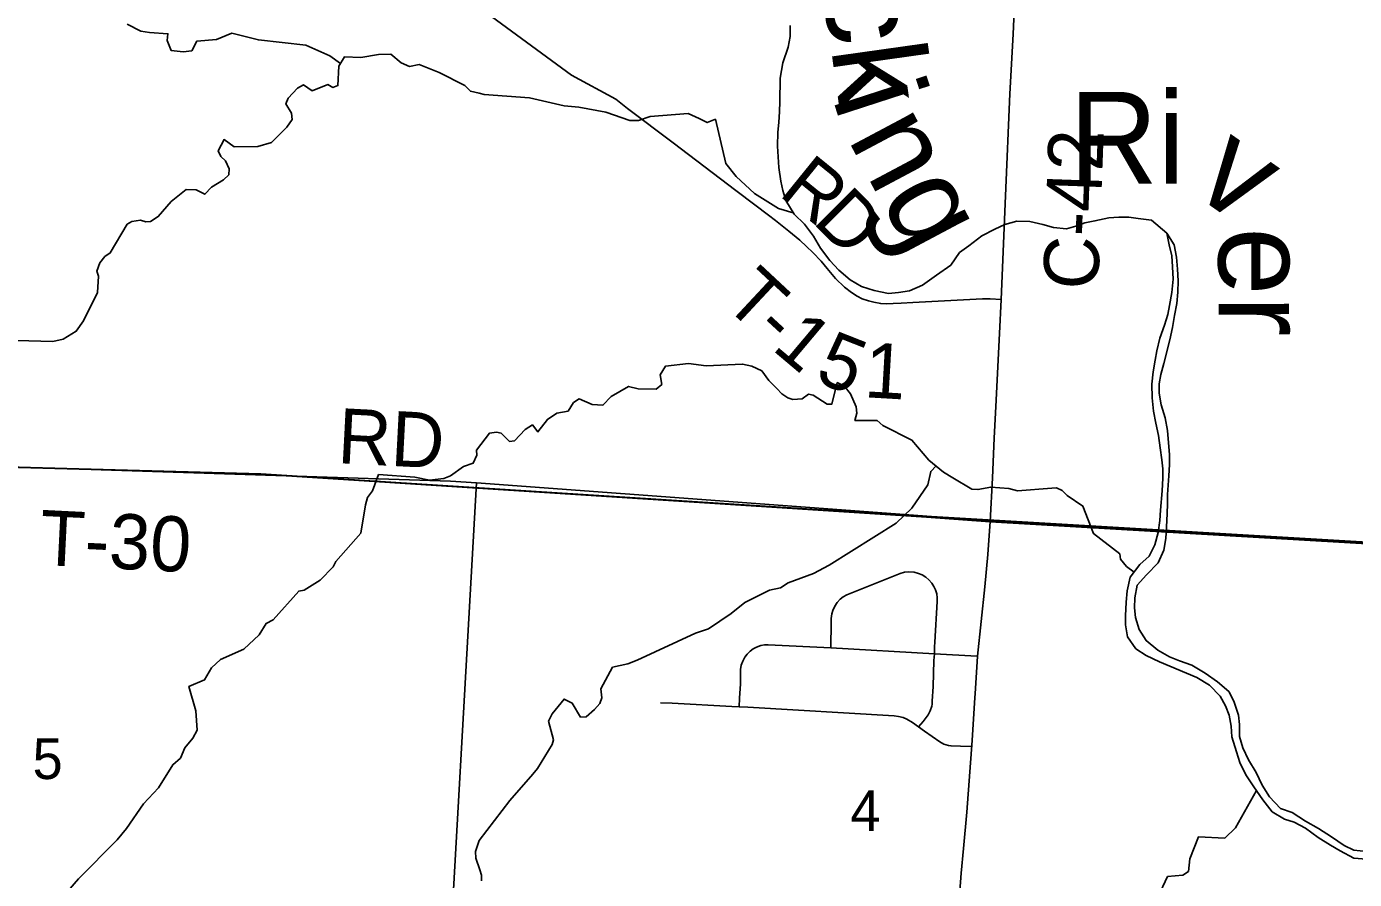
# Model space of a CAD drawing. Extents: x 0 to 34, y 0 to 22.
# Drawn here: x 6.826 to 8.197, y 17.774 to 18.654 of the extents above; entities that cross this region are included whole.
import ezdxf

# ---------------------------------------------------------------- set-up
doc = ezdxf.new("R2010")
doc.units = 0
for name, color, linetype in [('GM_X_Corporation', 7, 'Continuous'), ('GM_X_County_Road', 7, 'Continuous'), ('GM_X_County_Road_Text', 7, 'Continuous'), ('GM_X_Major_River', 7, 'Continuous'), ('GM_X_Major_River_Text', 7, 'Continuous'), ('GM_X_Minor_River', 7, 'Continuous'), ('GM_X_Section', 7, 'Continuous'), ('GM_X_Section_Text', 7, 'Continuous'), ('GM_X_Township_Road', 7, 'Continuous'), ('GM_X_Township_Road_Text', 7, 'Continuous')]:
    doc.layers.add(name, color=color, linetype=linetype)

msp = doc.modelspace()

# ---------------------------------------------------------------- linework, layer by layer
at = {"layer": 'GM_X_Corporation'}
msp.add_lwpolyline([(8.9, 18.0808), (8.9, 20.9), (6.4385, 20.9), (6.4325, 20.8009), (6.4277, 20.7531), (6.4097, 20.4361), (6.4016, 20.3608), (6.4001, 20.2844), (6.3927, 20.2003), (6.389, 20.1539), (6.3883, 20.1254), (6.385, 20.0884), (6.3621, 19.6044), (6.3556, 19.5188), (6.3374, 19.2897), (6.3253, 19.1073), (6.2646, 18.2231), (6.7672, 18.2007), (7.0679, 18.1923), (7.755, 18.1483), (7.8208, 18.1434), (8.8282, 18.0842)], close=True, dxfattribs=at)
msp.add_lwpolyline([(6.624, 15.6351), (6.838, 15.6206), (7.6503, 15.5653), (8.6741, 15.4976), (8.9, 15.4827), (8.9, 18.0808), (8.8282, 18.0842), (7.8208, 18.1434), (7.755, 18.1483), (7.0679, 18.1923), (6.7672, 18.2007)], dxfattribs=at)
at = {"layer": 'GM_X_County_Road'}
for points in [[(7.821, 18.1428), (7.8233, 18.1883), (7.8252, 18.229), (7.8271, 18.2684), (7.8288, 18.303), (7.8304, 18.3371), (7.8323, 18.3721), (7.8366, 18.479), (7.8412, 18.5844), (7.8445, 18.6458), (7.847, 18.7012)], [(7.8055, 17.9654), (7.8079, 18.0041), (7.8155, 18.0758), (7.8185, 18.1091), (7.82, 18.1285), (7.821, 18.1428)], [(7.7561, 17.2894), (7.7569, 17.2976), (7.7584, 17.3144), (7.7604, 17.3425), (7.7621, 17.3671), (7.7668, 17.4443), (7.7715, 17.549), (7.7739, 17.5845), (7.7759, 17.6032), (7.779, 17.6404), (7.7811, 17.6605), (7.7856, 17.7091), (7.7883, 17.7434), (7.7911, 17.7802), (7.7933, 17.8057), (7.7967, 17.8433), (7.8023, 17.9171), (7.8052, 17.9615), (7.8055, 17.9654)]]:
    msp.add_lwpolyline(points, dxfattribs=at)
at = {"layer": 'GM_X_Major_River'}
for points in [[(7.6144, 18.6548), (7.6143, 18.6434), (7.6123, 18.6324), (7.6069, 18.6162), (7.6041, 18.6006), (7.6039, 18.576), (7.6035, 18.5661), (7.6026, 18.5547), (7.6018, 18.5449), (7.6013, 18.5305), (7.6027, 18.5084), (7.6048, 18.4944), (7.607, 18.4845), (7.61, 18.4742), (7.6186, 18.4601), (7.6291, 18.4498), (7.6385, 18.4376), (7.6459, 18.425), (7.6553, 18.4124), (7.6647, 18.4025), (7.6764, 18.3925), (7.688, 18.3856), (7.7013, 18.3813), (7.716, 18.3782), (7.7262, 18.3793), (7.7376, 18.3811), (7.7509, 18.387), (7.7654, 18.3972), (7.7802, 18.4077), (7.7894, 18.4205), (7.799, 18.4276), (7.8123, 18.4378), (7.8256, 18.4449), (7.8359, 18.4494), (7.8484, 18.4531), (7.862, 18.4526), (7.8752, 18.4494), (7.8862, 18.4463), (7.8998, 18.4451), (7.9093, 18.4477), (7.9188, 18.4514)], [(7.9188, 18.4514), (7.929, 18.4532), (7.9435, 18.4565), (7.9537, 18.4572), (7.9639, 18.4571), (7.9738, 18.4559), (7.9874, 18.4539), (8.0033, 18.4407)], [(8.0033, 18.4407), (8.0057, 18.4287), (8.0083, 18.4173), (8.0093, 18.4057), (8.01, 18.393), (8.0084, 18.3794), (8.006, 18.3661), (8.0044, 18.3566), (8.0009, 18.3457), (7.9959, 18.3321), (7.9928, 18.3192), (7.9912, 18.3097), (7.9892, 18.2976), (7.9879, 18.2847), (7.9882, 18.2707), (7.9896, 18.257), (7.9918, 18.2444), (7.9947, 18.2319), (7.9965, 18.219), (7.9983, 18.2068), (7.999, 18.1973), (7.9993, 18.1879), (7.9985, 18.1746), (7.9968, 18.1549), (7.9959, 18.1443), (7.9943, 18.1317), (7.9908, 18.1189), (7.9851, 18.1072), (7.9755, 18.0989), (7.9656, 18.0857), (7.9624, 18.0717), (7.9612, 18.0599), (7.9607, 18.0459), (7.9606, 18.0364), (7.9628, 18.0242), (7.9714, 18.0117), (7.982, 18.0047), (7.9956, 17.9982), (8.0341, 17.982), (8.0473, 17.9743), (8.0582, 17.9628), (8.0638, 17.9529), (8.0678, 17.9434), (8.0697, 17.932), (8.0703, 17.921), (8.0751, 17.9054), (8.0788, 17.8944), (8.0848, 17.8818), (8.093, 17.8692), (8.1024, 17.8559), (8.1121, 17.8436), (8.1246, 17.836), (8.1348, 17.8328), (8.1465, 17.8267), (8.1596, 17.8171), (8.1721, 17.809), (8.1823, 17.8033), (8.1962, 17.7956), (8.2095, 17.7947)], [(8.2095, 17.8027), (8.1963, 17.8039), (8.1865, 17.8089), (8.1733, 17.8178), (8.1597, 17.8262), (8.1465, 17.8339), (8.1326, 17.8427), (8.1205, 17.847), (8.1092, 17.8592), (8.1017, 17.871), (8.0954, 17.884), (8.0876, 17.8973), (8.0816, 17.9095), (8.0783, 17.9213), (8.0784, 17.9338), (8.0773, 17.9433), (8.0725, 17.9578), (8.0673, 17.9677), (8.0556, 17.9776), (8.0428, 17.9868), (8.0292, 17.9949), (8.0164, 17.9992), (8.0062, 18.0034), (7.9941, 18.0103), (7.9821, 18.0203), (7.9746, 18.0317), (7.9709, 18.0439), (7.9699, 18.0542), (7.9703, 18.0644), (7.9727, 18.0773), (7.9823, 18.0882), (7.9945, 18.1006), (8.0002, 18.1135), (8.0022, 18.1256), (8.0031, 18.1374), (8.0036, 18.1514), (8.004, 18.1613), (8.0041, 18.1711), (8.0046, 18.1806), (8.0054, 18.1901), (8.0062, 18.2018), (8.0059, 18.2121), (8.0049, 18.2242), (8.0039, 18.2371), (8.0017, 18.2501), (7.9973, 18.2634), (7.9955, 18.2755), (7.9955, 18.285), (7.9971, 18.2949), (8.0002, 18.3062), (8.0065, 18.3305), (8.0092, 18.3433), (8.0112, 18.3558), (8.0136, 18.368), (8.0148, 18.3797), (8.0149, 18.3915), (8.0142, 18.4036), (8.0132, 18.4158), (8.011, 18.4287), (8.0033, 18.4407)]]:
    msp.add_lwpolyline(points, dxfattribs=at)
at = {"layer": 'GM_X_Minor_River'}
for points in [[(7.1501, 18.6156), (7.1393, 18.6235), (7.1143, 18.6346), (7.0655, 18.64), (7.0379, 18.6469), (7.0223, 18.6405), (7.0019, 18.6386), (6.9966, 18.6288), (6.9879, 18.6277), (6.9754, 18.6292), (6.9712, 18.6395), (6.972, 18.6463), (6.9531, 18.6475), (6.944, 18.649), (6.93, 18.6563)], [(7.6176, 18.4617), (7.6025, 18.4661), (7.5775, 18.4814), (7.5586, 18.4989), (7.5481, 18.5125), (7.5372, 18.5581), (7.5288, 18.5547), (7.5205, 18.5589), (7.5092, 18.5639), (7.4698, 18.5609), (7.458, 18.5568), (7.4489, 18.5568), (7.4243, 18.5656), (7.3963, 18.5706), (7.3812, 18.5721), (7.3452, 18.5802), (7.2987, 18.5837), (7.2934, 18.5849), (7.2843, 18.5871), (7.2786, 18.5929), (7.2521, 18.6062), (7.2313, 18.6146), (7.2215, 18.6127), (7.2128, 18.6165), (7.2022, 18.6253), (7.1893, 18.6249), (7.1711, 18.6219), (7.1545, 18.6227), (7.1484, 18.6129), (7.1476, 18.5928), (7.1423, 18.5909), (7.137, 18.5939), (7.1211, 18.5875), (7.112, 18.5936), (7.1059, 18.5902), (7.0961, 18.58), (7.0938, 18.5739), (7.0998, 18.5644), (7.1002, 18.558), (7.0949, 18.55), (7.0789, 18.5341), (7.0649, 18.5299), (7.0403, 18.5296), (7.0301, 18.5372), (7.024, 18.5255), (7.0266, 18.5198), (7.0316, 18.5152), (7.0353, 18.5069), (7.0349, 18.5008), (7.0296, 18.4955), (7.0171, 18.4879), (7.0103, 18.4807), (7.0012, 18.4853), (6.991, 18.4857), (6.9754, 18.4732), (6.9621, 18.4577), (6.9542, 18.4528), (6.9493, 18.4524), (6.9436, 18.4539), (6.9349, 18.4528), (6.9299, 18.4498), (6.9125, 18.4202), (6.9071, 18.4164), (6.9018, 18.41), (6.8988, 18.4013), (6.9003, 18.3963), (6.8995, 18.3793), (6.885, 18.3501), (6.8775, 18.3394), (6.8638, 18.3311), (6.8532, 18.3289), (6.8161, 18.3297)], [(7.9694, 18.0908), (7.9615, 18.0968), (7.9554, 18.1044), (7.9547, 18.1097), (7.9275, 18.1306), (7.9166, 18.1591), (7.9003, 18.1701), (7.8954, 18.1751), (7.8893, 18.1778), (7.8844, 18.1774), (7.8492, 18.1748), (7.8401, 18.1771), (7.8215, 18.1787), (7.8083, 18.176), (7.8019, 18.1764), (7.7822, 18.1883), (7.7727, 18.194), (7.7576, 18.2065), (7.7402, 18.2271), (7.71, 18.2423), (7.7043, 18.2473), (7.6812, 18.2473), (7.6831, 18.2549), (7.6827, 18.2614), (7.6767, 18.275), (7.6703, 18.283), (7.6631, 18.2864), (7.6574, 18.2641), (7.6525, 18.2641), (7.6381, 18.2736), (7.6332, 18.2744), (7.6267, 18.2698), (7.6172, 18.2691), (7.6119, 18.2706), (7.6059, 18.2748), (7.6006, 18.2805), (7.5923, 18.2885), (7.5851, 18.2984), (7.5749, 18.3033), (7.5654, 18.3056), (7.5276, 18.3038), (7.5094, 18.3062), (7.4859, 18.3035), (7.4802, 18.2944), (7.4821, 18.2846), (7.476, 18.2797), (7.4575, 18.2801), (7.4476, 18.2824), (7.4298, 18.2722), (7.4211, 18.2631), (7.4101, 18.2639), (7.3965, 18.2696), (7.3908, 18.2658), (7.3851, 18.2571), (7.3737, 18.2548), (7.3639, 18.2484), (7.354, 18.2355), (7.3483, 18.2427), (7.3407, 18.2382), (7.3297, 18.2265), (7.3248, 18.2257), (7.3161, 18.2341), (7.3112, 18.2352), (7.304, 18.2341), (7.2907, 18.2167), (7.2911, 18.2114), (7.2873, 18.2034), (7.2771, 18.2), (7.2638, 18.1902), (7.257, 18.1875), (7.2422, 18.1857), (7.227, 18.1887), (7.1896, 18.1915), (7.1831, 18.1748), (7.1782, 18.168), (7.1762, 18.1604), (7.1713, 18.1312), (7.1455, 18.102), (7.1428, 18.0963), (7.1291, 18.0827), (7.1128, 18.0721), (7.1071, 18.0713), (7.0806, 18.0418), (7.0734, 18.038), (7.0662, 18.0263), (7.0506, 18.0115), (7.0263, 18.0009), (7.0172, 17.9922), (7.01, 17.9797), (6.9937, 17.9729), (7.0009, 17.9478), (7.0023, 17.9277), (6.9978, 17.9194), (6.9894, 17.9095), (6.9849, 17.8989), (6.9773, 17.8921), (6.9625, 17.8682), (6.9469, 17.8519), (6.9294, 17.8265), (6.9196, 17.8148), (6.8797, 17.7746)], [(7.765, 18.2004), (7.7595, 18.1948), (7.7564, 18.1811), (7.7401, 18.1568), (7.7238, 18.1413), (7.6548, 18.0982), (7.6385, 18.0895), (7.6123, 18.0797), (7.6044, 18.0748), (7.593, 18.0722), (7.5676, 18.0597), (7.5536, 18.0483), (7.53, 18.0324), (7.5168, 18.0279), (7.4565, 18), (7.4467, 17.9962), (7.4311, 17.9928), (7.419, 17.9704), (7.4201, 17.9613), (7.4178, 17.9553), (7.4125, 17.9492), (7.4038, 17.9416), (7.3981, 17.9413), (7.3894, 17.9557), (7.3811, 17.9599), (7.3689, 17.9447), (7.3648, 17.9372), (7.37, 17.9178), (7.3689, 17.9129), (7.3537, 17.8882), (7.3487, 17.8825), (7.3252, 17.8553), (7.2933, 17.814), (7.2895, 17.8026), (7.2899, 17.7957), (7.294, 17.7836), (7.2959, 17.7783), (7.2959, 17.7722)], [(8.0957, 17.8654), (8.0742, 17.827), (8.0632, 17.8164), (8.0359, 17.8176), (8.0271, 17.7952), (8.0256, 17.782), (8.0199, 17.7782), (8.004, 17.7767), (7.9941, 17.7555)], [(6.8797, 17.7746), (6.8623, 17.7542), (6.852, 17.7311), (6.8523, 17.7235), (6.847, 17.7083), (6.8402, 17.7049), (6.836, 17.6992), (6.8114, 17.6879)]]:
    msp.add_lwpolyline(points, dxfattribs=at)
at = {"layer": 'GM_X_Section'}
for points in [[(6.2624, 18.2212), (6.7545, 18.2014), (7.2638, 18.1848), (7.2905, 18.1831), (7.2571, 17.593), (6.7148, 17.6287), (6.2291, 17.6617)], [(7.2905, 18.1831), (7.7604, 18.1481), (8.3042, 18.1163), (8.2754, 17.5329), (7.7498, 17.5639), (7.2571, 17.593)]]:
    msp.add_lwpolyline(points, close=True, dxfattribs=at)
at = {"layer": 'GM_X_Township_Road'}
msp.add_line((8.8284, 18.0837), (7.821, 18.1428), dxfattribs=at)
for points in [[(7.8323, 18.3721), (7.8208, 18.3727), (7.8131, 18.3727), (7.7607, 18.3701), (7.741, 18.3689), (7.7289, 18.3683), (7.7209, 18.3681), (7.7136, 18.3678), (7.7079, 18.3679), (7.7009, 18.3693), (7.6953, 18.3709), (7.6889, 18.373), (7.6835, 18.3755), (7.6777, 18.3794), (7.6707, 18.385), (7.6614, 18.3939), (7.6526, 18.4042), (7.6464, 18.4116), (7.638, 18.4206), (7.6313, 18.4269), (7.6244, 18.4333), (7.6131, 18.4427), (7.6043, 18.4496), (7.5993, 18.4538), (7.5919, 18.4591), (7.578, 18.4697), (7.5582, 18.4845), (7.4935, 18.5337), (7.4464, 18.5692), (7.4344, 18.5788), (7.3888, 18.6035), (7.3008, 18.6681)], [(7.821, 18.1428), (7.7552, 18.1477), (7.0681, 18.1918), (6.7674, 18.2001)], [(7.6563, 18.0128), (7.6567, 18.0391), (7.6569, 18.0432), (7.6575, 18.0478), (7.6584, 18.0514), (7.6604, 18.0557), (7.663, 18.0596), (7.6661, 18.063), (7.6692, 18.0655), (7.673, 18.0676), (7.7279, 18.0893), (7.7326, 18.0907), (7.7371, 18.0911), (7.7424, 18.0907), (7.7468, 18.0896), (7.7508, 18.0881), (7.7545, 18.0858), (7.7577, 18.0829), (7.7608, 18.0794), (7.7628, 18.0761), (7.7645, 18.0727), (7.7657, 18.0685), (7.7662, 18.0643), (7.7661, 18.0607), (7.7638, 18.0185), (7.7635, 18.0138), (7.7635, 18.0067), (7.7628, 17.9997), (7.7619, 17.973), (7.7612, 17.9576), (7.7611, 17.9547), (7.7607, 17.9525), (7.7591, 17.9478), (7.7568, 17.9436), (7.7518, 17.9369), (7.747, 17.9314)], [(7.5617, 17.9519), (7.5623, 17.961), (7.563, 17.9757), (7.5632, 17.9799), (7.563, 17.9871), (7.5632, 17.9905), (7.564, 17.995), (7.5655, 17.9991), (7.5676, 18.0031), (7.5701, 18.0064), (7.573, 18.0094), (7.5762, 18.0116), (7.5798, 18.0136), (7.5841, 18.0151), (7.5881, 18.0159), (7.5918, 18.016), (7.6563, 18.0128), (7.7635, 18.0067), (7.7698, 18.0062), (7.8011, 18.0044), (7.8079, 18.0041)], [(7.4807, 17.9559), (7.4925, 17.9557), (7.5541, 17.9522), (7.5617, 17.9519), (7.5707, 17.9514), (7.7219, 17.9425), (7.7264, 17.9419), (7.7311, 17.941), (7.735, 17.9393), (7.7409, 17.9359), (7.747, 17.9314), (7.7532, 17.9267), (7.7689, 17.9157), (7.773, 17.9135), (7.7778, 17.9121), (7.7806, 17.9116), (7.7903, 17.9112), (7.8019, 17.9109)]]:
    msp.add_lwpolyline(points, dxfattribs=at)

# ---------------------------------------------------------------- texts
at = {"layer": 'GM_X_County_Road_Text'}
msp.add_text('C-42', height=0.05682, rotation=87.9422, dxfattribs=at).set_placement((7.9323, 18.3817))
at = {"layer": 'GM_X_Major_River_Text'}
for s, height, rotation, p in [('ck', 0.09469, 278.0005, (7.6477, 18.6941)), ('i', 0.0947, 288.0008, (7.6577, 18.5805)), ('Ri', 0.09469, 0.0007, (7.9025, 18.4917)), ('ng', 0.09469, 298.0011, (7.6731, 18.5386)), ('v', 0.0947, 325.0011, (8.027, 18.4838)), ('er', 0.09469, 269.9999, (8.0567, 18.4467))]:
    msp.add_text(s, height=height, rotation=rotation, dxfattribs=at).set_placement(p)
at = {"layer": 'GM_X_Section_Text'}
for s, p in [('5', (6.8323, 17.8774)), ('4', (7.6765, 17.8239))]:
    msp.add_text(s, height=0.0419, rotation=0, dxfattribs=at).set_placement(p)
at = {"layer": 'GM_X_Township_Road_Text'}
for s, height, rotation, p in [('R', 0.0568, 320.986, (7.6014, 18.4804)), ('D', 0.0568, 314.8789, (7.6365, 18.4521)), ('T', 0.0568, 316.9975, (7.5438, 18.3681)), ('-', 0.0568, 317.2827, (7.5751, 18.3389)), ('1', 0.0568, 319.9409, (7.5944, 18.3212)), ('5', 0.0568, 338.4757, (7.6384, 18.2884)), ('1', 0.0568, 356.693, (7.6901, 18.2714)), ('RD', 0.05682, 357.0388, (7.1464, 18.2034)), ('T-30', 0.05682, 357.1731, (6.8387, 18.0984))]:
    msp.add_text(s, height=height, rotation=rotation, dxfattribs=at).set_placement(p)

doc.saveas('drawing.dxf')
